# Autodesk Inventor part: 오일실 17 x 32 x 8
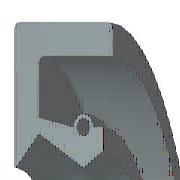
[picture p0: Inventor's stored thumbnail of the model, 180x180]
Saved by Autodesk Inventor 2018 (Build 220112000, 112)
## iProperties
IsCustomPart: 1
Created: 2012-02
Part Number: 오일실 17 x 32 x 8
Material: 고무
Description: 오일-실
Document SubType Name: Modeling
Standard: KS B 2804
Designer: mduedu
Standards Organization: KS
Language: ko-KR
Size Designation: D - 17 32 8
Categories: <MemberInstance><Categories><Category DisplayName="샤프트 부품" InternalName="7f7aeb1f-a693-4053-b835-cee3144e0d98" Mnemonic="SHFT"><Category DisplayName="실링" Intern
Density: 0.93 g/cm^3
Appearance: 고무 - 검은색 - 버전 1.1
Author: mduedu
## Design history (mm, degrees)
revolve "본체" stored, may be unused: angle "d17" = 90 deg
revolve "스프링1" stored, may be unused: angle "d18" = 90 deg
body "Solid1"
sketch "스케치1"
  geometry: L1 (0, 16)-(8, 16); L2 (8, 14.25)-(1.75, 14.25); L3 (1.75, 10.25)-(4.9, 8.5); L4 (4.9, 8.5)-(0, 8.5); L5 (0, 0)-(9.586, 0) reference; L6 (4.9, 8.5)-(6.3, 9.375); L7 (0, 18)-(0, -3) reference; L8 (-1.941, 0)-(11.507, 0) reference; L9 (4.2, 10.6)-(1.75, 11.21); L10 (1.75, 11.21)-(1.75, 14.25); L11 (0, 16)-(0, 8.588); L12 (4.9, 8.5)-(0, 8.5); L13 (1.75, 10.25)-(0.152, 8.528); L14 (8, 16)-(8, 14.25); L15 (5.6, 10.6)-(6.3, 10.6); L16 (6.3, 10.6)-(6.3, 9.375); C1 r 0.455 at (4.9, 10.6); A1 r 0.7 centre (4.9, 10.6) between (5.6, 10.6) and (4.2, 10.6); A2 r 0.088 centre (0.088, 8.588) between (0, 8.588) and (0.152, 8.528); 1 further point
  constraints: 28 end point, 5 horizontal alignment, 5 point on line, 4 point on circle, 4 vertical alignment, 3 centre point, 3 tangent, 2 collinear, 2 horizontal, 2 perpendicular, 1 coincident, 1 parallel
  dimensions: "d0" = 32 diameter of L1 L5 (= SD2); "d1" = 1.75 distance of L1.end L2.start (= SD); "d2" = 0.91 diameter of C1 (= SPDI); "d3" = 1.4 diameter of A1 (= SPDA); "d4" = 17 diameter of L3.end L5 (= NND); "d5" = 20.5 diameter of L3.start L5 (= TKDM); "d7" = 22.42 diameter of L9.end L5 (= TKDM + 0.24 x SWDT); "d8" = 1.75 distance between parallel lines of L11 L10 (= SD); "d9" = 4.9 distance from line of L11 C1.centre (= SPDST); "d10" = 21.2 diameter of C1.centre L5 (= HLDM); "d11" = 0.0875 radius of A2 (= 0.25 x LAB); "d12" = 6.3 distance between parallel lines of L11 L16 (= SDI); "d13" = 18.75 diameter of L6.end L5 (= ABDM); "d14" = 8 distance from line of L11 L1.end (= SWDT)
fillet "모깎기1" dims "d6" = 0.3 (= RR)
other parameters: "SD2" = 32 [user parameter; used in 1 equation term], "SWDT" = 8 [user parameter; used in 2 equation terms], "RR" = 0.3 [user parameter; used in 1 equation term], "SD" = 1.75 [user parameter; used in 2 equation terms], "NND" = 17 [user parameter; used in 1 equation term], "SPDA" = 1.4 [user parameter; used in 1 equation term], "SPDI" = 0.91 [user parameter; used in 1 equation term], "TKDM" = 20.5 [user parameter; used in 2 equation terms], "HLDM" = 21.2 [user parameter; used in 1 equation term], "ABDM" = 18.75 [user parameter; used in 1 equation term], "SDI" = 6.3 [user parameter; used in 1 equation term], "SPDST" = 4.9 [user parameter; used in 1 equation term], "LAB" = 0.35 [user parameter; used in 1 equation term], "d15" = 0, "d16" = 0, "d19" = 0
